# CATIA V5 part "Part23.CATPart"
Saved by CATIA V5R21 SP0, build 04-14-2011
Part number: Part23
Bounding box of the stored display mesh (mm): x 0 to 11, y -5 to 5, z -5 to 5
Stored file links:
  C:\Users\水心\Desktop\Arm_Detailed_Design_Assembly_Manu\CAD\Part23.CATPart
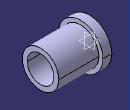
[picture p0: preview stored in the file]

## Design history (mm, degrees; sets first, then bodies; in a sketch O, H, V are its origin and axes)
Body1 (main body)
  Sketch1 on yz-plane, origin (0, 0, 0), H (0, 1, 0), V (0, 0, 1)
    circle A1 centre (0, 0) radius 5
    circle A2 centre (0, 0) radius 3
    radius A1 = 5
    radius A2 = 3
  Pad1: profile Sketch1, direction (1, 0, 0), length 2
  Sketch2 on end face of Pad1, origin (2, 0, 0), H (0, 1, 0), V (0, 0, 1)
    circle A1 centre (0, 0) radius 4.1
    circle A2 centre (0, 0) radius 3
    radius A1 = 4.1
    radius A2 = 3
  Pad2: profile Sketch2, direction (1, 0, 0), length 9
